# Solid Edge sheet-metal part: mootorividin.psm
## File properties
Author: Indrek
Template: Normal.psm
Last saved by: Indrek
Revision: 1
Application: Solid Edge
Accuracy: 0,990
Material Thickness: 1,00 mm
Bend Radius: 1,00 mm
Relief Width: 1,00 mm
Relief Length: 0,00 mm
Neutral Factor: 0,330
Minimum Arc Length: 0,10 mm
Deviational Tolerance: 0,10 mm
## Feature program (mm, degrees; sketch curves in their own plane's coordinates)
base tab "unnamed BaseTab 1"
jog tab "JogTab_2"  OffsetDistance = 1.6741 mm
louver "Louver_1"  LouverDepth = 4 mm; LouverHeight = 2.6313 mm
jog tab "JogTab_3"  OffsetDistance = 2.5518 mm
flange "Flange_2"
flange "Flange_3"
sheet metal cutout "SheetMetalCutout_1"
sheet metal cutout "SheetMetalCutout_2"
dimple "Dimple_2"
bead "unnamed Bead 1"
pattern "unnamed Pattern 1" of "unnamed Bead 1"
bead "unnamed Bead 2"
bead "unnamed Bead 3"
bead "unnamed Bead 4"
bead "unnamed Bead 5"
bead "unnamed Bead 6"
bead "unnamed Bead 7"
bead "unnamed Bead 8"
bead "unnamed Bead 9"
bead "unnamed Bead 10"
bead "unnamed Bead 11"
bead "unnamed Bead 12"
break corner "BreakCorner_1"  SetBackValue1 = 2 mm
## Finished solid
Body 1: solid body, 280 faces, 624 edges, 370 vertices.
  Faces by surface: plane 101, cylinder 69, torus 50, cone 48, spline 8, sphere 4
  Edges by curve: line 308, circle 278, curve on surface 30, ellipse 8
Bounding box of the edges (mm; curved faces can reach further): 30.000 x 55.552 x 8.482, from (-15.082, -5.552, -2.5518) to (14.918, 50, 5.9305).
Cylindrical faces by radius (mm): R1 x54, R2 x6, R2.5 x1, R3.356 x1, R3.5 x1, R4.356 x1, R11.9602 x1, R58.0027 x2, R70.5847 x2
Conical faces (half-angle, radius in mm at the cone's reference point): 15 deg R0.3014 x12, 15 deg R0.6363 x12, 15 deg R1.2673 x12, 15 deg R1.6023 x12
Toroidal faces (ring radius, tube radius in mm): R0.5 r1 x24, R1.6023 r1 x24, R2.5 r1 x1, R3.5 r1 x1
Spherical faces by radius (mm): R3.356 x2, R4.356 x2
Planar faces by outward normal: +x 3, +y 2, +z 17, -x 3, -y 3, -z 17, oblique 56
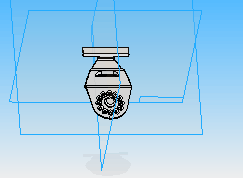
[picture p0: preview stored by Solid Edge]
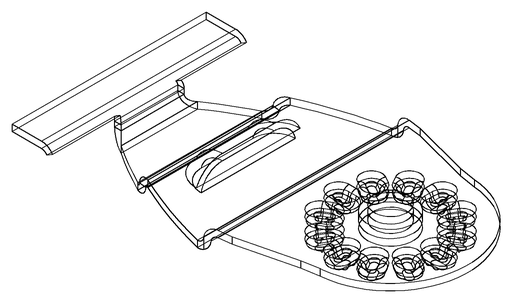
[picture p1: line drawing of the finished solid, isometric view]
